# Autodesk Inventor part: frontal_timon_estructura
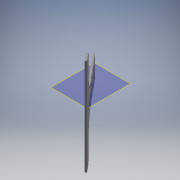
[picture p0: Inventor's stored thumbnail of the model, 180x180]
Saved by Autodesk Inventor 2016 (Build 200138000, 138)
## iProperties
Created: 2017-06
Part Number: frontal_timon_estructura
Material: Generic
Document SubType Name: Modeling
Designer: laboratorioesan
Density: 1 g/cm^3
Appearance: Default
Author: laboratorioesan
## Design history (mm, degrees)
sketch "Sketch1"
  geometry: L1 (-29.189, -4.822)-(-51.614, 22.05) reference; L2 (-47.008, 25.895)-(-22.981, -2.897) reference; L3 (-10.409, -15.199)-(29.692, 18.266) reference; L4 (-43.009, -16.355)-(-65.434, 10.517) reference; L5 (-70.041, 6.673)-(-45.325, -22.944) reference; L6 (-47.008, 25.895)-(-70.041, 6.673) reference; L7 (-31.652, 38.709)-(-432.262, 518.759); L8 (-432.262, 518.759)-(-420.361, 528.69); L9 (-420.361, 528.69)-(-19.752, 48.64); L10 (-31.652, 38.709)-(-19.752, 48.64); L11 (-1131.104, 152.556)-(-641.104, 152.556) reference; L12 (-220.057, 288.665)-(-231.957, 278.734); 1 further point
  constraints: 18 end point, 2 midpoint, 1 parallel, 1 perpendicular, 12 other
  dimensions: "d0" = 20 distance between parallel lines of L7 L2; "d1" = 15.5 distance of L7.end L8.end
extrude "Extrusion1" new body sketch "Sketch1" stored distance "d2" = 200; taper "d3" = 0 deg
sketch "Sketch2"
  geometry: L1 (200, 0)-(0, 0) reference; L2 (0, -312.624)-(0, 0) reference; L3 (200, -312.624)-(0, -312.624) reference; L4 (200, 0)-(200, -312.624) reference; L5 (20, -40)-(35.5, -40); L6 (35.5, -40)-(35.5, -90); L7 (35.5, -90)-(20, -90); L8 (20, -90)-(20, -40); L9 (20, -140)-(35.5, -140); L10 (35.5, -140)-(35.5, -190); L11 (35.5, -190)-(20, -190); L12 (20, -190)-(20, -140); L13 (20, -240)-(35.5, -240); L14 (35.5, -240)-(35.5, -290); L15 (35.5, -290)-(20, -290); L16 (20, -290)-(20, -240); L17 (164.5, -40)-(180, -40); L18 (180, -40)-(180, -90); L19 (180, -90)-(164.5, -90); L20 (164.5, -90)-(164.5, -40); L21 (164.5, -140)-(180, -140); L22 (180, -140)-(180, -190); L23 (180, -190)-(164.5, -190); L24 (164.5, -190)-(164.5, -140); L25 (164.5, -240)-(180, -240); L26 (180, -240)-(180, -290); L27 (180, -290)-(164.5, -290); L28 (164.5, -290)-(164.5, -240); 1 further point
  constraints: 48 end point, 12 parallel, 6 horizontal, 6 horizontal alignment, 6 perpendicular, 5 vertical alignment, 4 point on line
  dimensions: "d4" = 15.5 distance of L6.end L7.end; "d5" = 50 distance of L5.end L6.end; "d6" = 20 horizontal distance of L1.end L5.start; "d7" = 40 vertical distance of L1.end L5.start; "d8" = 50 distance of L9.end L10.end; "d9" = 50 distance between parallel lines of L9 L7; "d10" = 50 distance of L13.end L14.end; "d11" = 50 distance between parallel lines of L13 L11; "d12" = 15.5 distance of L18.end L19.end; "d13" = 20 horizontal distance of L1.start L17.end
extrude "Extrusion2" cut sketch "Sketch2" distance "d14" = 15.5; taper "d15" = 0 deg
sketch "Sketch3"
  geometry: L1 (-318.5, -237.627)-(518.5, -237.627) reference; L2 (164.5, -190)-(164.5, -140) reference; L3 (164.5, -140)-(180, -140) reference; L4 (180, -140)-(180, -190) reference; L5 (180, -190)-(164.5, -190) reference; L6 (20, -290)-(20, -240) reference; L7 (20, -240)-(35.5, -240) reference; L8 (35.5, -240)-(35.5, -290) reference; L9 (35.5, -290)-(20, -290) reference; L10 (20, -90)-(20, -40) reference; L11 (20, -40)-(35.5, -40) reference; L12 (35.5, -40)-(35.5, -90) reference; L13 (35.5, -90)-(20, -90) reference; L14 (20, -190)-(20, -140) reference; L15 (20, -140)-(35.5, -140) reference; L16 (35.5, -140)-(35.5, -190) reference; L17 (35.5, -190)-(20, -190) reference; L18 (164.5, -90)-(164.5, -40) reference; L19 (164.5, -40)-(180, -40) reference; L20 (180, -40)-(180, -90) reference; L21 (180, -90)-(164.5, -90) reference; L22 (164.5, -290)-(164.5, -240) reference; L23 (164.5, -240)-(180, -240) reference; L24 (180, -240)-(180, -290) reference; L25 (180, -290)-(164.5, -290) reference; L26 (200, 0)-(0, 0) reference; L27 (0, -312.624)-(0, 0) reference; L28 (200, -312.624)-(0, -312.624) reference; L29 (200, 0)-(200, -312.624) reference; L30 (0, -312.624)-(200, -312.624); L31 (200, -312.624)-(200, -452.624); L32 (200, -452.624)-(0, -452.624); L33 (0, -452.624)-(0, -312.624); L34 (20, -350)-(35.5, -350); L35 (35.5, -350)-(35.5, -400); L36 (35.5, -400)-(20, -400); L37 (20, -400)-(20, -350); L38 (164.5, -350)-(180, -350); L39 (180, -350)-(180, -400); L40 (180, -400)-(164.5, -400); L41 (164.5, -400)-(164.5, -350); 1 further point
  constraints: 24 end point, 6 parallel, 3 horizontal, 3 perpendicular, 1 horizontal alignment
  dimensions: "d16" = 140 distance of L30.end L31.end; "d17" = 50 distance of L34.end L35.end; "d18" = 60 distance of L6.start L34.start; "d19" = 50 distance of L38.end L39.end
extrude "Extrusion3" join sketch "Sketch3" distance "d20" = 15.5; taper "d21" = 0 deg
workplane "Work Plane1"
sketch "Sketch4"
  geometry: L1 (432.262, 518.759)-(142.256, 171.246) reference; L2 (432.262, 518.759)-(420.361, 528.69) reference; L3 (420.361, 528.69)-(130.356, 181.177) reference; L4 (130.356, 181.177)-(142.256, 171.246) reference; L5 (-32.55, 77.056)-(199.272, 77.056) reference; L6 (142.256, 171.246)-(63.654, 77.056); L7 (51.753, 86.987)-(130.356, 181.177); L8 (51.753, 86.987)-(63.654, 77.056); 1 further point
  constraints: 6 end point, 1 parallel, 1 perpendicular, 1 point on line
extrude "Extrusion4" join sketch "Sketch4" stored distance "d22" = 880; taper "d23" = 0 deg
fillet "Fillet1" dims "d24" = 120
fillet "Fillet2" dims "d25" = 50
sketch "Sketch5"
  geometry: L1 (-340, -575.303)-(-340, -502.624) reference; L2 (-340, -575.303)-(540, -575.303) reference; L3 (540, -502.624)-(540, -575.303) reference; L4 (320, -452.624)-(490, -452.624) reference; L5 (200, 0)-(200, -332.624) reference; L6 (200, 0)-(0, 0) reference; L7 (0, 0)-(0, -332.624) reference; L8 (-290, -452.624)-(-120, -452.624) reference; L9 (20, -400)-(20, -350) reference; L10 (20, -350)-(35.5, -350) reference; L11 (35.5, -350)-(35.5, -400) reference; L12 (35.5, -400)-(20, -400) reference; L13 (164.5, -400)-(164.5, -350) reference; L14 (164.5, -350)-(180, -350) reference; L15 (180, -350)-(180, -400) reference; L16 (180, -400)-(164.5, -400) reference; L17 (164.5, -190)-(164.5, -140) reference; L18 (164.5, -140)-(180, -140) reference; L19 (180, -140)-(180, -190) reference; L20 (180, -190)-(164.5, -190) reference; L21 (20, -290)-(20, -240) reference; L22 (20, -240)-(35.5, -240) reference; L23 (35.5, -240)-(35.5, -290) reference; L24 (35.5, -290)-(20, -290) reference; L25 (20, -90)-(20, -40) reference; L26 (20, -40)-(35.5, -40) reference; L27 (35.5, -40)-(35.5, -90) reference; L28 (35.5, -90)-(20, -90) reference; L29 (20, -190)-(20, -140) reference; L30 (20, -140)-(35.5, -140) reference; L31 (35.5, -140)-(35.5, -190) reference; L32 (35.5, -190)-(20, -190) reference; L33 (164.5, -90)-(164.5, -40) reference; L34 (164.5, -40)-(180, -40) reference; L35 (180, -40)-(180, -90) reference; L36 (180, -90)-(164.5, -90) reference; L37 (164.5, -290)-(164.5, -240) reference; L38 (164.5, -240)-(180, -240) reference; L39 (180, -240)-(180, -290) reference; L40 (180, -290)-(164.5, -290) reference; L41 (115, -625.249)-(85, -625.249) reference; L42 (85, -625.249)-(85, -676.342) reference; L43 (115, -625.249)-(115, -676.342) reference; L44 (80, -90.5)-(120, -90.5); L45 (120, -90.5)-(120, -75); L46 (120, -75)-(80, -75); L47 (80, -75)-(80, -90.5); L48 (80, -226)-(120, -226); L49 (120, -226)-(120, -210.5); L50 (120, -210.5)-(80, -210.5); L51 (80, -210.5)-(80, -226); L52 (80, -361.5)-(120, -361.5); L53 (120, -361.5)-(120, -346); L54 (120, -346)-(80, -346); L55 (80, -346)-(80, -361.5); L56 (80, -497)-(120, -497); L57 (120, -497)-(120, -481.5); L58 (120, -481.5)-(80, -481.5); L59 (80, -481.5)-(80, -497); A1 r 50 centre (-290, -502.624) between (-290, -452.624) and (-340, -502.624) reference; A2 r 50 centre (490, -502.624) between (540, -502.624) and (490, -452.624) reference; A3 r 120 centre (320, -332.624) between (200, -332.624) and (320, -452.624) reference; A4 r 120 centre (-120, -332.624) between (-120, -452.624) and (0, -332.624) reference; 4 further points
  constraints: 36 end point, 8 parallel, 4 horizontal, 4 perpendicular, 3 midpoint, 2 point on line, 2 vertical, 2 vertical alignment, 2 other
  dimensions: "d26" = 40 distance of L46.end L45.end; "d27" = 15.5 distance of L45.end L44.end; "d28" = 40 distance of L50.end L49.end; "d29" = 15.5 distance of L49.end L48.end; "d30" = 40 distance of L54.end L53.end; "d31" = 15.5 distance of L53.end L52.end; "d32" = 40 distance of L58.end L57.end; "d33" = 15.5 distance of L57.end L56.end; "d34" = 120 distance of L44.start L50.end; "d35" = 120 distance between parallel lines of L48 L54; "d36" = 120 distance between parallel lines of L52 L58
extrude "Extrusion5" cut sketch "Sketch5" distance "d37" = 15.5; taper "d38" = 0 deg
body "Solid1"
node "Reference1"
node "Reference2"
node "Reference3"
node "Projected Loop1"
node "Reference4"
node "Projected Loop2"
node "Projected Loop3"
node "Reference5"
node "Projected Loop4"
node "Reference6"
